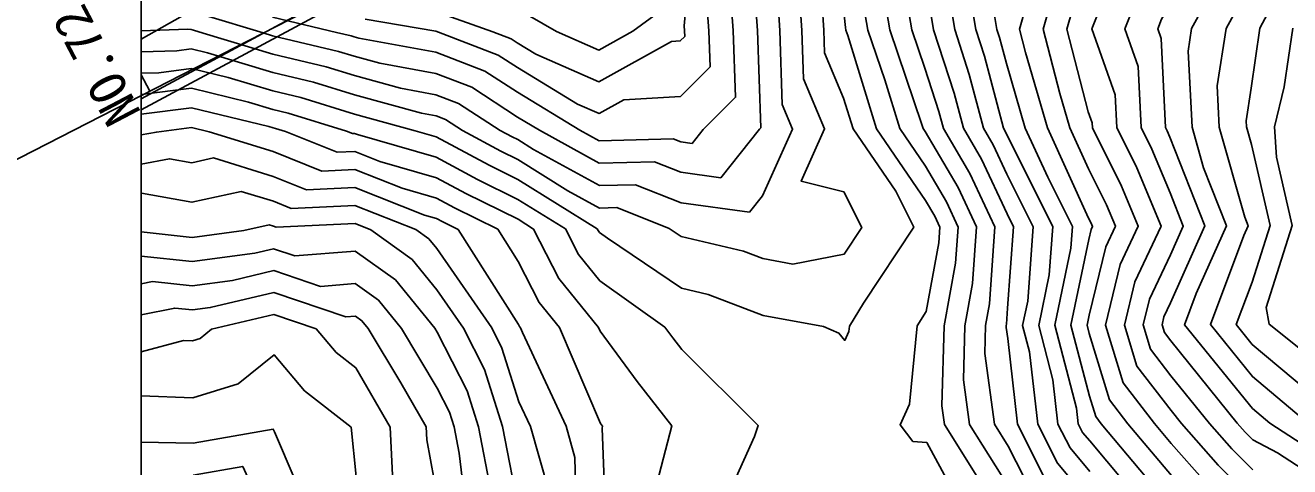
# Model space of a CAD drawing. Extents: x 42655 to 43811, y -141820 to -141156.
# Drawn here: x 42717.4 to 42796.3, y -141670.4 to -141642.9 of the extents above; entities that cross this region are included whole.
import ezdxf

# ---------------------------------------------------------------- set-up
doc = ezdxf.new("R2010")
doc.units = 0
for name, color, linetype in [('D-BMK-HTXT_1', 7, 'Continuous'), ('D-STR-STR2トンネル', 7, 'Continuous'), ('D-TTL', 7, 'Continuous'), ('ZE_HICN', 7, 'Continuous'), ('ZE_LWCN', 7, 'Continuous'), ('着色', 7, 'Continuous')]:
    doc.layers.add(name, color=color, linetype=linetype)

msp = doc.modelspace()

# ---------------------------------------------------------------- linework, layer by layer
at = {"layer": 'D-BMK-HTXT_1'}
for p, q in [((42777.191, -141614.053), (42724.628, -141643.736)), ((42725.14, -141646.957), (42724.628, -141645.982))]:
    msp.add_line(p, q, dxfattribs=at)
at = {"layer": 'D-STR-STR2トンネル'}
for points in [[(42724.628, -141647.478), (42760.547, -141628.171)], [(42724.628, -141648.156), (42760.837, -141628.697)]]:
    msp.add_lwpolyline(points, dxfattribs=at)
at = {"layer": 'D-TTL'}
msp.add_lwpolyline([(42724.63, -141820.399), (43685.83, -141820.386), (43685.821, -141155.586), (42724.621, -141155.599), (42724.63, -141820.399)], dxfattribs=at)
at = {"layer": 'ZE_HICN'}
for points in [[(42798.902, -141626.221), (42795.789, -141630.729), (42794.8, -141631.897), (42793.843, -141632.56), (42790.693, -141634.579), (42788.771, -141636.09), (42788.318, -141636.376), (42786.864, -141636.933), (42785.536, -141639.167), (42783.963, -141643.109), (42785.426, -141647.217), (42785.521, -141649.265), (42786.771, -141651.77), (42788.291, -141655.415), (42786.654, -141658.892), (42785.999, -141661.588), (42786.78, -141664.154), (42788.915, -141666.931), (42789.563, -141667.734), (42791.86, -141670.338), (42794.029, -141672.519)], [(42797.674, -141636.883), (42796.215, -141639.722), (42794.464, -141643.06), (42793.909, -141646.814), (42793.595, -141648.835), (42793.615, -141649.227), (42793.926, -141650.324), (42795.097, -141655.383), (42793.966, -141658.916), (42792.98, -141661.555), (42793.984, -141662.795), (42797.426, -141665.688)], [(42762.707, -141637.81), (42763.09, -141643.207), (42763.312, -141649.273), (42763.216, -141649.369), (42760.808, -141652.397), (42758.316, -141652.054), (42756.664, -141651.396), (42753.225, -141651.488), (42749.487, -141649.433), (42748.123, -141648.605), (42745.26, -141646.747), (42743.022, -141645.884), (42739.523, -141645.245), (42737.929, -141644.81), (42736.954, -141644.507), (42732.834, -141643.531), (42732.235, -141643.35), (42728.649, -141642.266)], [(42776.25, -141640.283), (42776.729, -141643.143), (42777.265, -141644.799), (42778.444, -141649.298), (42778.532, -141649.448), (42778.658, -141649.716), (42781.535, -141655.446), (42781.31, -141658.446), (42780.654, -141661.613), (42781.543, -141665.017), (42781.856, -141667.77), (42782.608, -141669.255), (42783.844, -141670.728)], [(42769.721, -141641.628), (42769.991, -141643.174), (42771.044, -141646.293), (42771.979, -141649.328), (42773.579, -141651.669), (42774.887, -141653.905), (42775.625, -141655.474), (42775.468, -141657.728), (42774.749, -141661.64), (42774.615, -141666.633), (42774.778, -141667.803), (42778.147, -141673.198)], [(42756.68, -141671.956), (42757.742, -141667.882), (42755.587, -141665.108), (42753.273, -141661.971), (42753.175, -141661.741), (42750.696, -141658.693), (42749.126, -141655.597), (42748.153, -141654.991), (42744.903, -141653.38), (42743.052, -141652.391), (42739.526, -141651.376), (42737.956, -141650.757), (42736.87, -141650.808), (42733.627, -141649.506), (42733.02, -141649.317), (42732.861, -141649.28), (42732.606, -141649.203), (42727.767, -141648.036), (42724.628, -141648.437)], [(42746.451, -141671.94), (42745.676, -141667.938), (42744.967, -141665.697), (42743.097, -141662.033), (42742.951, -141661.788), (42740.496, -141658.769), (42737.985, -141656.971), (42734.226, -141657.274), (42732.896, -141656.823), (42731.723, -141657.1), (42727.812, -141657.629), (42724.628, -141657.285)], [(42735.466, -141674.148), (42732.949, -141668.26), (42732.872, -141668.091), (42727.864, -141668.959), (42724.628, -141668.897)]]:
    msp.add_lwpolyline(points, dxfattribs=at)
at = {"layer": 'ZE_LWCN'}
for points in [[(42796.48, -141624.563), (42793.823, -141628.228), (42792.794, -141629.49), (42791.572, -141630.749), (42788.756, -141632.962), (42786.605, -141634.321), (42783.68, -141635.441), (42779.771, -141636.966), (42779.898, -141641.581), (42779.456, -141643.13), (42779.826, -141644.573), (42781.2, -141649.285), (42783.77, -141654.912), (42783.934, -141655.239), (42784.015, -141655.434), (42783.927, -141655.621), (42783.777, -141656.241), (42782.665, -141661.603), (42783.822, -141666.034), (42784.208, -141667.299), (42784.56, -141667.757), (42788.943, -141672.982)], [(42797.567, -141624.558), (42793.83, -141629.713), (42793.41, -141630.228), (42792.911, -141630.742), (42788.761, -141634.005), (42787.176, -141635.006), (42783.684, -141636.343), (42782.116, -141636.955), (42782.167, -141638.807), (42780.935, -141643.123), (42781.967, -141647.141), (42782.59, -141649.278), (42783.756, -141651.83), (42784.879, -141654.083), (42785.44, -141655.428), (42784.836, -141656.711), (42783.799, -141660.982), (42783.671, -141661.599), (42783.804, -141662.108), (42785.065, -141666.251), (42786.217, -141667.75), (42788.934, -141670.988)], [(42791.018, -141671.367), (42788.924, -141668.993), (42787.874, -141667.742), (42785.923, -141665.202), (42784.824, -141661.593), (42785.745, -141657.802), (42786.866, -141655.421), (42785.825, -141652.926), (42784.002, -141649.272), (42783.989, -141648.974), (42783.74, -141648.275), (42782.414, -141643.117), (42783.695, -141638.629), (42784.146, -141637.498), (42784.475, -141636.944), (42787.747, -141635.691), (42788.766, -141635.047), (42793.091, -141631.647), (42793.836, -141631.169), (42794.063, -141631.012), (42794.297, -141630.736), (42796.794, -141627.12)], [(42797.281, -141630.722), (42795.538, -141632.781), (42793.849, -141633.951), (42789.214, -141636.922), (42788.779, -141637.719), (42786.927, -141640.835), (42786.023, -141643.1), (42786.863, -141645.459), (42787.04, -141649.258), (42787.716, -141650.614), (42788.851, -141653.335), (42789.671, -141655.408), (42788.869, -141657.207), (42787.563, -141659.982), (42787.174, -141661.582), (42787.638, -141663.105), (42788.905, -141664.754), (42791.306, -141667.726), (42792.702, -141669.309), (42794.02, -141670.634)], [(42798.773, -141630.715), (42796.275, -141633.666), (42793.856, -141635.343), (42791.407, -141636.912), (42788.797, -141641.695), (42788.317, -141642.503), (42788.083, -141643.09), (42788.301, -141643.702), (42788.559, -141649.251), (42788.662, -141649.457), (42788.835, -141649.873), (42791.021, -141655.402), (42788.883, -141660.198), (42788.472, -141661.073), (42788.349, -141661.577), (42788.495, -141662.057), (42788.894, -141662.576), (42793.048, -141667.718), (42793.544, -141668.279), (42794.012, -141668.75), (42795.553, -141669.568), (42799.114, -141671.881)], [(42797.012, -141634.55), (42793.862, -141636.734), (42793.6, -141636.902), (42793.075, -141637.865), (42790.199, -141643.08), (42789.979, -141644.497), (42790.223, -141649.243), (42790.941, -141651.779), (42792.37, -141655.396), (42790.488, -141659.621), (42789.759, -141661.57), (42794.002, -141666.81), (42795.072, -141667.708), (42799.107, -141670.328)], [(42797.75, -141635.435), (42795.647, -141636.892), (42794.964, -141638.221), (42793.879, -141640.29), (42792.346, -141643.07), (42791.787, -141646.666), (42791.919, -141649.235), (42793.512, -141654.864), (42793.72, -141655.389), (42793.446, -141656.003), (42791.369, -141661.563), (42793.993, -141664.803), (42797.438, -141667.697)], [(42759.032, -141637.063), (42758.525, -141642.922), (42758.547, -141643.228), (42758.56, -141643.571), (42758.277, -141643.852), (42757.739, -141643.884), (42753.201, -141646.403), (42749.267, -141644.679), (42748.101, -141643.971), (42747.728, -141643.729), (42746.572, -141643.283), (42743.004, -141642.008)], [(42764.155, -141638.027), (42764.49, -141643.2), (42764.646, -141647.833), (42765.287, -141649.359), (42763.411, -141653.52), (42762.597, -141654.543), (42758.324, -141653.956), (42755.492, -141652.828), (42753.231, -141652.889), (42749.116, -141650.625), (42748.129, -141650.012), (42747.794, -141649.845), (42747.043, -141649.444), (42744.437, -141647.753), (42743.028, -141647.21), (42740.825, -141646.807), (42737.934, -141646.018), (42736.167, -141645.469), (42732.84, -141644.681), (42728.494, -141643.368), (42727.896, -141643.187), (42727.744, -141643.151), (42727.545, -141643.131), (42724.628, -141643.222)], [(42774.6, -141638.302), (42775.411, -141643.149), (42776.32, -141645.956), (42777.197, -141649.304), (42777.803, -141650.34), (42778.669, -141652.181), (42780.311, -141655.452), (42779.965, -141660.092), (42779.649, -141661.617), (42780.077, -141663.258), (42780.59, -141667.776), (42781.825, -141670.212), (42783.853, -141672.63)], [(42761.313, -141639.514), (42761.576, -141643.214), (42761.728, -141647.372), (42759.707, -141649.385), (42759.019, -141650.25), (42758.307, -141650.152), (42757.835, -141649.964), (42753.218, -141650.087), (42752.006, -141649.421), (42748.116, -141647.06), (42746.083, -141645.741), (42743.016, -141644.559), (42738.221, -141643.683), (42737.923, -141643.602), (42737.741, -141643.545), (42736.828, -141643.329), (42732.829, -141642.382)], [(42771.99, -141638.854), (42772.741, -141643.162), (42773.55, -141645.557), (42774.428, -141648.268), (42774.703, -141649.315), (42776.345, -141652.122), (42777.917, -141655.463), (42777.582, -141660.265), (42777.332, -141661.628), (42777.285, -141663.368), (42777.899, -141667.788), (42778.748, -141669.148), (42780.259, -141672.127)], [(42765.646, -141639.817), (42765.866, -141643.194), (42765.967, -141646.218), (42767.282, -141649.35), (42765.817, -141652.6), (42768.498, -141653.278), (42769.61, -141655.502), (42768.516, -141657.156), (42765.3, -141657.785), (42763.429, -141657.443), (42762.227, -141656.989), (42758.334, -141656.07), (42757.578, -141655.558), (42754.321, -141654.26), (42753.238, -141654.289), (42751.266, -141653.205), (42748.135, -141651.257), (42747.072, -141650.729), (42744.688, -141649.455), (42743.614, -141648.758), (42743.034, -141648.535), (42742.127, -141648.369), (42737.94, -141647.227), (42735.38, -141646.431), (42732.845, -141645.831), (42728.769, -141644.599), (42727.75, -141644.353), (42726.848, -141644.468), (42724.628, -141644.543)], [(42770.856, -141640.241), (42771.366, -141643.168), (42773.359, -141649.07), (42773.437, -141649.321), (42773.569, -141649.514), (42775.616, -141653.014), (42776.771, -141655.468), (42776.525, -141658.996), (42776.04, -141661.634), (42775.95, -141665.001), (42776.338, -141667.796), (42778.76, -141671.674)], [(42773.523, -141639.752), (42774.093, -141643.155), (42775.374, -141647.112), (42775.95, -141649.309), (42777.074, -141651.231), (42778.681, -141654.646), (42779.088, -141655.457), (42778.708, -141660.543), (42778.639, -141661.533), (42778.623, -141661.622), (42778.62, -141661.736), (42778.717, -141662.436), (42779.324, -141667.782), (42781.042, -141671.17)], [(42767.138, -141641.607), (42767.241, -141643.187), (42767.288, -141644.603), (42768.471, -141647.418), (42769.063, -141649.341), (42771.728, -141653.242), (42772.851, -141655.486), (42769.718, -141660.226), (42768.834, -141661.668), (42768.802, -141661.988), (42768.541, -141662.55), (42768.186, -141662.098), (42767.218, -141661.675), (42763.445, -141660.985), (42760.018, -141659.691), (42758.349, -141659.297), (42753.737, -141656.169), (42753.245, -141655.819), (42753.146, -141655.698), (42753.085, -141655.578), (42748.141, -141652.501), (42746.349, -141651.613), (42743.04, -141649.845), (42741.734, -141649.469), (42737.946, -141648.435), (42734.593, -141647.393), (42732.85, -141646.98), (42730.048, -141646.134), (42727.756, -141645.581), (42725.726, -141645.84), (42724.628, -141645.877)], [(42759.919, -141641.218), (42760.061, -141643.221), (42760.144, -141645.472), (42758.294, -141647.314), (42754.763, -141647.523), (42753.21, -141648.385), (42751.864, -141647.795), (42748.109, -141645.516), (42746.905, -141644.735), (42743.18, -141643.299), (42743.01, -141643.239), (42738.602, -141642.492)], [(42748.891, -141642.307), (42750.553, -141643.265), (42753.192, -141644.422), (42755.315, -141643.243), (42757.165, -141641.897)], [(42768.444, -141641.672), (42768.587, -141643.015), (42768.616, -141643.181), (42768.729, -141643.515), (42770.521, -141649.335), (42773.589, -141653.824), (42774.158, -141654.797), (42774.479, -141655.479), (42774.411, -141656.46), (42773.621, -141660.755), (42773.074, -141661.648), (42772.593, -141666.535), (42771.997, -141667.816), (42772.795, -141668.858), (42773.659, -141668.929), (42776.399, -141673.958)], [(42777.901, -141642.263), (42778.047, -141643.137), (42778.211, -141643.643), (42778.637, -141645.269), (42779.81, -141649.291), (42781.214, -141652.366), (42782.758, -141655.44), (42782.656, -141656.801), (42781.66, -141661.608), (42783.009, -141666.776), (42783.121, -141667.764), (42783.392, -141668.297), (42783.835, -141668.826), (42788.094, -141673.903)], [(42796.507, -141643.051), (42795.964, -141646.727), (42795.369, -141649.219), (42795.492, -141651.111), (42796.48, -141655.376), (42794.84, -141660.497), (42795.046, -141661.546), (42799.081, -141664.755)], [(42760.445, -141674.032), (42762.905, -141668.556), (42763.142, -141667.857), (42758.367, -141663.117), (42757.806, -141662.395), (42757.309, -141661.721), (42753.259, -141658.84), (42751.921, -141657.195), (42751.105, -141655.588), (42748.147, -141653.746), (42745.626, -141652.497), (42743.046, -141651.118), (42738.132, -141649.704), (42737.951, -141649.632), (42737.826, -141649.638), (42737.453, -141649.489), (42733.806, -141648.355), (42732.856, -141648.13), (42731.327, -141647.668), (42727.761, -141646.808), (42724.628, -141647.209)], [(42753.642, -141674.064), (42753.399, -141668.021), (42753.43, -141667.902), (42753.368, -141667.821), (42753.3, -141667.73), (42750.74, -141661.752), (42749.47, -141660.191), (42748.165, -141657.616), (42746.89, -141655.607), (42744.18, -141654.264), (42743.058, -141653.664), (42740.92, -141653.049), (42737.962, -141651.882), (42735.913, -141651.977), (42732.868, -141650.755), (42728.871, -141649.528), (42727.773, -141649.263), (42725.579, -141649.544), (42724.628, -141649.722)], [(42751.798, -141674.072), (42751.697, -141669.864), (42751.146, -141667.913), (42748.435, -141662.065), (42748.306, -141661.763), (42748.245, -141661.689), (42748.183, -141661.566), (42744.408, -141655.619), (42743.458, -141655.148), (42743.064, -141654.938), (42742.314, -141654.722), (42737.967, -141653.006), (42734.957, -141653.146), (42732.875, -141652.311), (42729.132, -141651.162), (42727.783, -141651.456), (42726.404, -141651.209), (42724.628, -141651.541)], [(42750.044, -141671.885), (42748.924, -141667.923), (42748.206, -141666.374), (42747.148, -141663.031), (42746.506, -141661.772), (42743.073, -141656.811), (42742.586, -141656.213), (42741.774, -141655.631), (42737.972, -141654.131), (42734, -141654.316), (42732.883, -141653.867), (42730.872, -141653.25), (42727.794, -141653.921), (42724.647, -141653.357), (42724.628, -141653.361)], [(42748.238, -141673.369), (42747.186, -141667.931), (42746.058, -141664.364), (42744.739, -141661.78), (42743.085, -141659.39), (42741.541, -141657.491), (42738.963, -141655.644), (42737.977, -141655.255), (42733.044, -141655.485), (42732.89, -141655.423), (42732.612, -141655.338), (42731.041, -141655.681), (42727.805, -141656.119), (42724.628, -141655.776)], [(42745.023, -141674.104), (42744.483, -141669.579), (42744.166, -141667.945), (42743.877, -141667.03), (42743.113, -141665.534), (42740.874, -141661.798), (42739.45, -141660.047), (42737.995, -141659.005), (42735.815, -141659.18), (42732.903, -141658.192), (42730.333, -141658.8), (42727.819, -141659.14), (42725.342, -141658.872), (42724.628, -141659.014)], [(42743.146, -141672.499), (42742.463, -141668.759), (42742.424, -141667.953), (42740.826, -141665.192), (42738.797, -141661.808), (42738.405, -141661.326), (42738.004, -141661.038), (42737.404, -141661.087), (42732.909, -141659.562), (42728.943, -141660.499), (42727.826, -141660.65), (42726.725, -141660.531), (42724.628, -141660.947)], [(42740.328, -141671.37), (42740.162, -141667.964), (42738.019, -141664.261), (42736.792, -141663.298), (42735.543, -141661.823), (42732.915, -141660.931), (42729.015, -141661.853), (42728.305, -141662.427), (42727.835, -141662.571), (42727.266, -141662.55), (42724.628, -141663.271)], [(42724.628, -141666.013), (42727.851, -141666.133), (42730.674, -141665.269), (42732.927, -141663.447), (42734.831, -141665.696), (42737.737, -141667.975), (42738.051, -141671.055)], [(42732.681, -141674.161), (42730.97, -141670.416), (42727.874, -141670.953)]]:
    msp.add_lwpolyline(points, dxfattribs=at)
at = {"layer": '着色'}
msp.add_lwpolyline([(42760.837, -141628.697), (42654.786, -141683.055)], dxfattribs=at)

# ---------------------------------------------------------------- texts
at = {"layer": 'D-BMK-HTXT_1'}
msp.add_text('NO.72', height=2.3065, rotation=117.69467, dxfattribs=at).set_placement((42724.653, -141648.342))

doc.saveas('drawing.dxf')
